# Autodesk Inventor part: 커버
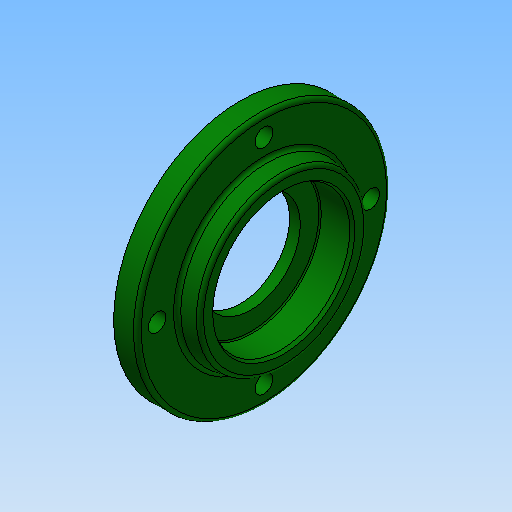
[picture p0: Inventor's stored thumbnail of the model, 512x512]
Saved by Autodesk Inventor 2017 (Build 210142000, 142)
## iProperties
Created: 2018-11
Part Number: 커버
Material: 알루미늄 6061
Document SubType Name: Modeling
Designer: mduedu
Density: 1 g/cm^3
Appearance: 진녹색
Author: mduedu
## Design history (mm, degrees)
sketch "스케치1"
  geometry: L1 (0, 0)-(3, 0); L2 (3, 0)-(3, 23.5); L3 (3, 23.5)-(0, 23.5); L4 (0, 23.5)-(0, 0); L5 (3, 0)-(9, 0); L6 (9, 0)-(9, 32); L7 (9, 32)-(3, 32); L8 (3, 32)-(3, 0); L9 (9, 0)-(14, 0); L10 (14, 0)-(14, 21.118); L11 (9, 22)-(9, 0); L12 (9, 22)-(14, 21.118)
  constraints: 24 end point, 5 parallel, 3 horizontal, 3 perpendicular
  dimensions: "d0" = 64 diameter of L7 L5; "d3" = 47 diameter of L3 L1; "d4" = 3 distance of L2.end L3.end; "d5" = 6 distance of L6.end L7.end; "d6" = 14 distance between parallel lines of L10 L4; "d37" = 44 diameter of L11.start L9; "d38" = 10 deg angle of L9 L12
revolve "회전1" sketch "스케치1" stored, may be unused: angle "d7" = 90 deg
sketch "스케치2"
  geometry: L1 (0, -23.5)-(0, 23.5) reference; L2 (0, 23.5)-(3, 23.5) reference; L3 (3, 23.5)-(3, 32) reference; L4 (3, 32)-(9, 32) reference; L5 (9, 32)-(9, 22) reference; L6 (9, -22)-(9, -32) reference; L7 (9, -32)-(3, -32) reference; L8 (3, -32)-(3, -23.5) reference; L9 (3, -23.5)-(0, -23.5) reference; L10 (0, 0)-(3, 0); L11 (3, 0)-(3, 20); L12 (3, 20)-(0, 20); L13 (0, 20)-(0, 0); L14 (3, 0)-(5.7, 0); L15 (5.7, 0)-(5.7, 12.5); L16 (5.7, 12.5)-(3, 12.5); L17 (3, 12.5)-(3, 0); L18 (5.7, 0)-(14, 0); L19 (14, 0)-(14, 17.5); L20 (14, 17.5)-(5.7, 17.5); L21 (5.7, 17.5)-(5.7, 0); L22 (9, 22)-(14, 21.118) reference; L23 (14, 21.118)-(14, -21.118) reference; L24 (14, -21.118)-(9, -22) reference
  constraints: 24 end point, 6 parallel, 3 horizontal, 3 perpendicular, 1 midpoint
  dimensions: "d8" = 35 diameter of L20 L18; "d10" = 25 diameter of L16 L14; "d11" = 40 diameter of L12 L10; "d12" = 3 distance of L11.end L12.end; "d13" = 8.3 distance of L19.end L20.end
revolve "회전2" sketch "스케치2" stored, may be unused: angle "d14" = 90 deg
fillet "모깎기1" dims "d15" = 0.3
chamfer "모따기1" distance "d16" = 0.8; stored, may be unused: second distance "d17" = 2, angle "d18" = 30 deg
fillet "모깎기2" dims "d19" = 1, "d35" = 3
chamfer "모따기2" distance "d20" = 0.5; stored, may be unused: second distance "d21" = 2, angle "d22" = 30 deg
sketch "스케치3" dims "d23" = 52
  geometry: 6 further points
  constraints: 2 vertical alignment, 1 coincident, 7 other
  dimensions: "d26" = 360 deg dimension on point (0, 0) point (0, 26) (derived)
sketch "스케치4" dims "d39" = 54
  geometry: C1 r 32 at (0, 0) reference; 5 further points
  constraints: 2 vertical alignment, 1 coincident, 7 other
  dimensions: "d43" = 360 deg dimension on C1.centre point (0, 27) (derived)
hole "구멍1" sketch "스케치4" at (0, 27), (-27, 0), (0, -27), (27, 0) diameter "d28" = 4.5; stored, may be unused: countersink angle "d32" = 90 deg, drill point angle "d34" = 0 deg; dims "d29" = 6, "d30" = 8, "d31" = 4.6, "d33" = 8
node "솔리드1"
node "절단 모서리 투영1"
